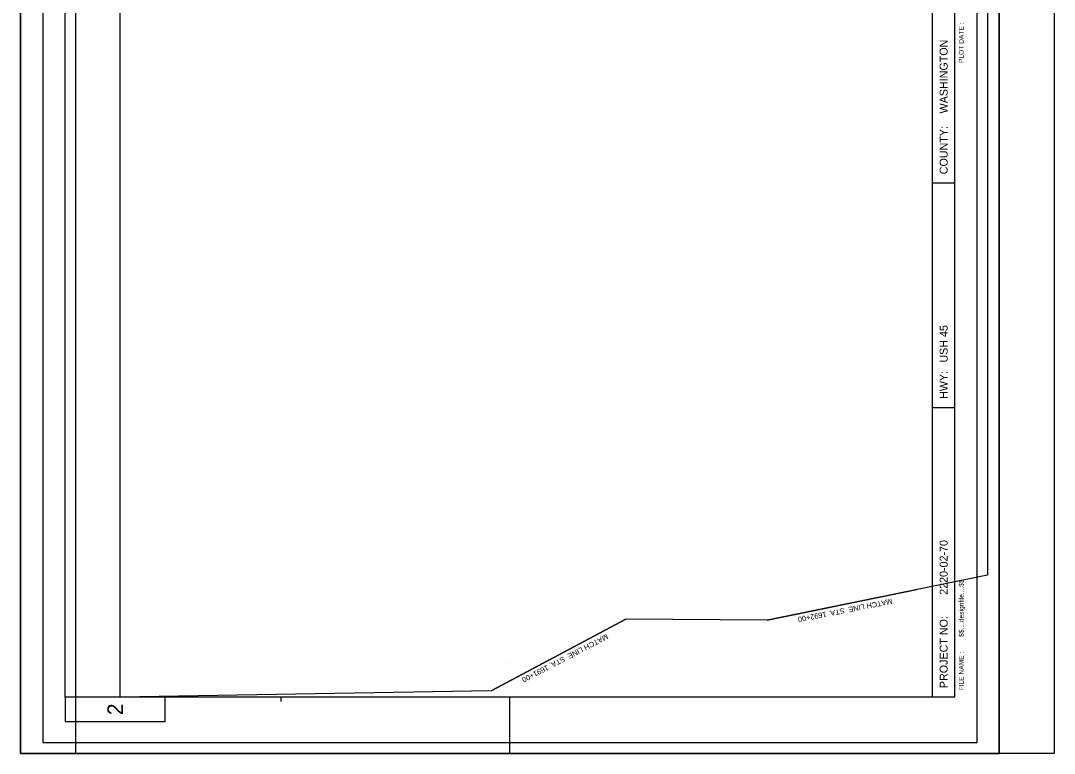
# Model space of a CAD drawing. Extents: x 361207 to 362369, y 128283 to 129983.
# Drawn here: x 361207 to 362369, y 128283 to 129106 of the extents above; entities that cross this region are included whole.
import ezdxf

# ---------------------------------------------------------------- set-up
doc = ezdxf.new("R2010")
doc.units = 0
for name, color, linetype in [('Default', 7, 'Continuous'), ('P_SHTIDX_1 [KAPUR_CADDS_LEVELS]', 7, 'Continuous'), ('P_SHTIDX_2 [KAPUR_CADDS_LEVELS]', 7, 'Continuous'), ('P_SHTIDX_3 [KAPUR_CADDS_LEVELS]', 7, 'Continuous'), ('P_TXT_Plan 3 [KAPUR_CADDS_LEVELS]', 7, 'Continuous'), ('P_TXT_Plan 4 [KAPUR_CADDS_LEVELS]', 7, 'Continuous'), ('P_TXT_Plan 4_TEXT [KAPUR_CADDS_LEVELS]', 7, 'Continuous')]:
    doc.layers.add(name, color=color, linetype=linetype)

msp = doc.modelspace()

# ---------------------------------------------------------------- linework, layer by layer
at = {"layer": 'Default'}
msp.add_lwpolyline([(361735.9, 128353.1), (361319.1, 128346.1), (361319.1, 129901.2), (361497.1, 129898), (361755.9, 129854.7), (362117.2, 129921.1), (362294.1, 129921.1), (362294.1, 128483.1), (362046.5, 128432.3), (361887.5, 128433.7)], close=True, dxfattribs=at)
msp.add_lwpolyline([(361735.9, 128353.1), (361319.1, 128346.1), (361319.1, 129901.2), (361497.1, 129898), (361755.9, 129854.7), (362117.2, 129921.1), (362294.1, 129921.1), (362294.1, 128483.1), (362046.5, 128432.3), (361887.5, 128433.7)], close=True, dxfattribs=at)
at = {"layer": 'P_SHTIDX_1 [KAPUR_CADDS_LEVELS]'}
msp.add_lwpolyline([(361269.1, 128282.8), (361269.1, 129982.8), (362369.1, 129982.8), (362369.1, 128282.8), (361269.1, 128282.8)], dxfattribs=at)
at = {"layer": 'P_SHTIDX_2 [KAPUR_CADDS_LEVELS]'}
for p, q in [((361257.2, 128346.1), (361257.2, 129921.1)), ((362232.2, 128346.1), (362232.2, 129921.1)), ((362257.2, 128346.1), (362257.2, 129921.1)), ((362257.2, 128923.6), (362232.2, 128923.6)), ((362257.2, 128671.1), (362232.2, 128671.1)), ((361757.2, 128383.6), (361757.2, 128383.6)), ((362257.2, 128346.1), (361257.2, 128346.1)), ((361499.7, 128346.1), (361499.7, 128341.1)), ((361757.2, 128282.8), (361757.2, 128346.1)), ((361207.2, 128282.8), (361207.2, 128332.8)), ((362307.2, 128282.8), (362307.2, 128332.8)), ((361257.2, 128282.8), (361207.2, 128282.8)), ((361782.2, 128282.8), (361732.2, 128282.8)), ((362307.2, 128282.8), (362257.2, 128282.8))]:
    msp.add_line(p, q, dxfattribs=at)
msp.add_lwpolyline([(361257.2, 128346.1), (361257.2, 128318.6), (361369.7, 128318.6), (361369.7, 128346.1)], close=True, dxfattribs=at)
at = {"layer": 'P_SHTIDX_3 [KAPUR_CADDS_LEVELS]'}
for points in [[(362307.2, 128282.8), (362307.2, 129982.8), (361207.2, 129982.8), (361207.2, 128282.8)], [(362282.2, 128294.8), (362282.2, 129949.8), (361232.2, 129949.8), (361232.2, 128294.8)]]:
    msp.add_lwpolyline(points, close=True, dxfattribs=at)
at = {"layer": 'P_TXT_Plan 4 [KAPUR_CADDS_LEVELS]'}
for p, q in [((362046.5, 128432.3), (362214.7, 128466.8)), ((361735.9, 128353.1), (361887.5, 128433.7))]:
    msp.add_line(p, q, dxfattribs=at)
at = {"layer": 'P_TXT_Plan 4_TEXT [KAPUR_CADDS_LEVELS]'}
msp.add_lwpolyline([(361207.2, 128282.8), (361207.2, 129982.8), (362307.2, 129982.8), (362307.2, 128282.8)], close=True, dxfattribs=at)

# ---------------------------------------------------------------- texts
at = {"layer": 'P_SHTIDX_2 [KAPUR_CADDS_LEVELS]'}
for s, height, p in [('PLOT DATE :', 5.4, (362267.2, 129058.6)), (' WASHINGTON', 9, (362249.2, 128998.6)), ('COUNTY:', 9, (362249.2, 128933.6)), (' USH 45', 9, (362249.2, 128718.6)), ('HWY:', 9, (362249.2, 128681.1)), (' 2220-02-70', 9, (362249.2, 128457.6)), ('$$....designfile....$$', 5.4, (362267.2, 128413.6)), ('PROJECT NO:', 9, (362249.2, 128356.1)), ('FILE NAME :', 5.4, (362267.2, 128353.6)), ('2', 17.5, (361322.2, 128325.8))]:
    msp.add_text(s, height=height, rotation=90, dxfattribs=at).set_placement(p)
at = {"layer": 'P_TXT_Plan 3 [KAPUR_CADDS_LEVELS]'}
for s, rotation, p in [('MATCH LINE  STA. 1692+00', 191.1335, (362186.4, 128456.8)), ('MATCH LINE  STA. 1691+00', 207.5147, (361865.7, 128417.3))]:
    msp.add_text(s, height=6, rotation=rotation, dxfattribs=at).set_placement(p)

doc.saveas('drawing.dxf')
